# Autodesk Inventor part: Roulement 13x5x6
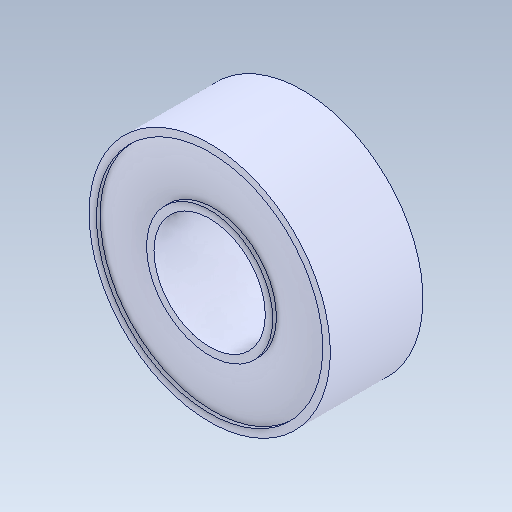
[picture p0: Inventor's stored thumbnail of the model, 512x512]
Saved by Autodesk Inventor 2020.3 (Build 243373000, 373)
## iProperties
Created: 2018-09
Part Number: Roulement 13x5x6
Material: Générique
Document SubType Name: Modeling
Designer: ficho
Density: 1 g/cm^3
Appearance: Par défaut
Mass: 0.51164 g
Surface Area: 5.33591 cm^2
Volume: 0.51164 cm^3
Sending System: SolidWorks 2015
Last Author: adrien
Last Saved: 2019-01-11
Author: ficho
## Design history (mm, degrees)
feature "Révolution1"
node "Solide1"
